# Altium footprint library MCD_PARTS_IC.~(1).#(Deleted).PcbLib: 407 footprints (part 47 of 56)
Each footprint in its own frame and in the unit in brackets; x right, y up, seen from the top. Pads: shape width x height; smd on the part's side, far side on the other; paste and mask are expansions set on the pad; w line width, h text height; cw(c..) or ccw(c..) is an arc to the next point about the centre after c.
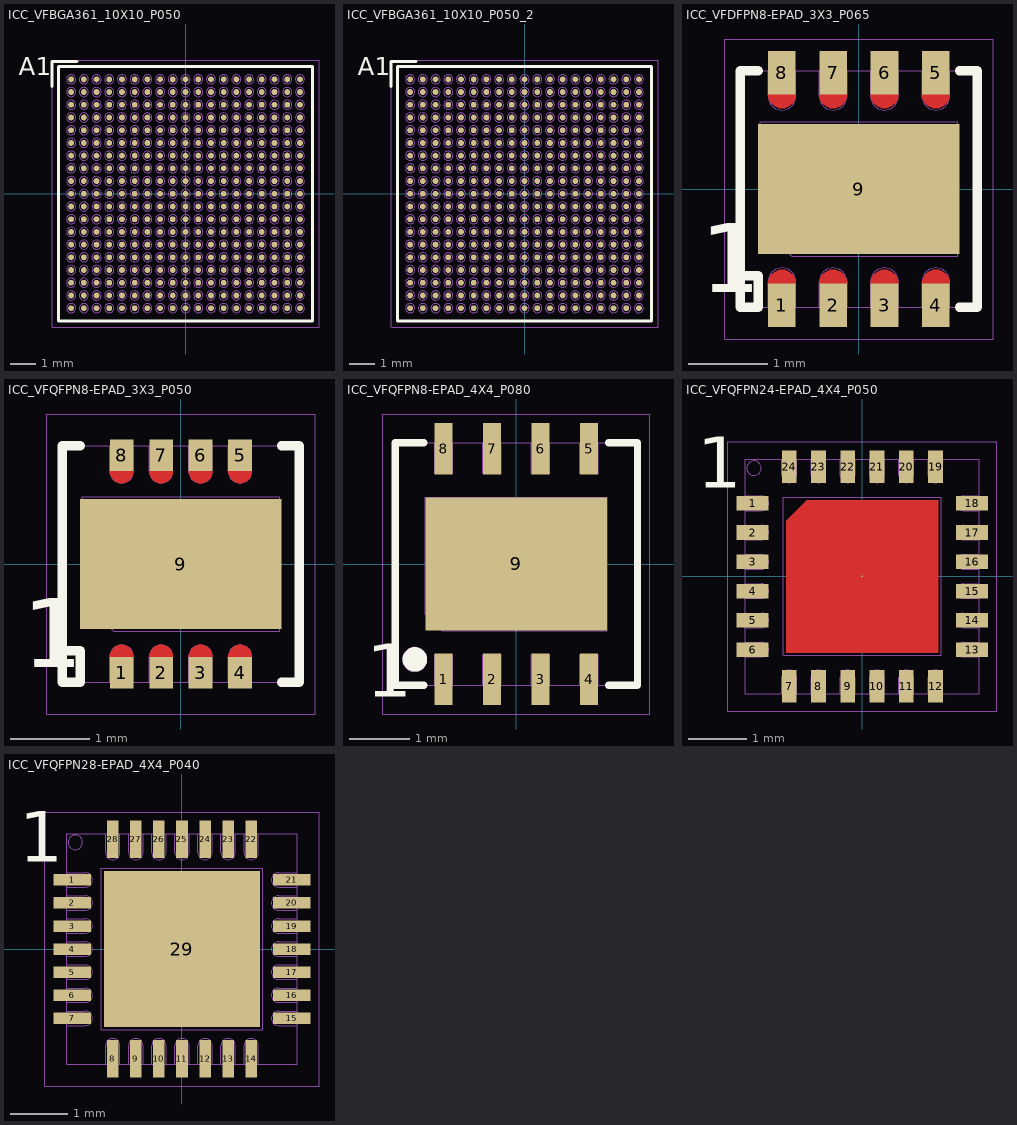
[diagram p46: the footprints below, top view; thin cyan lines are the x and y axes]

## ICC_VFBGA361_10X10_P050 [mm] "MCD-03768"
height 0.81
pads (361):
  round 0.23 smd mask+0.05: A1(-4.5,4.5) A2(-4,4.5) A3(-3.5,4.5) A4(-3,4.5) A5(-2.5,4.5) A6(-2,4.5) A7(-1.5,4.5) A8(-1,4.5) A9(-0.5,4.5) A10(0,4.5) A11(0.5,4.5) A12(1,4.5) A13(1.5,4.5) A14(2,4.5) A15(2.5,4.5) A16(3,4.5) A17(3.5,4.5) A18(4,4.5) A19(4.5,4.5) B1(-4.5,4) B2(-4,4) B3(-3.5,4) B4(-3,4) B5(-2.5,4) B6(-2,4) B7(-1.5,4) B8(-1,4) B9(-0.5,4) B10(0,4) B11(0.5,4) B12(1,4) B13(1.5,4) B14(2,4) B15(2.5,4) B16(3,4) B17(3.5,4) B18(4,4) B19(4.5,4) C1(-4.5,3.5) C2(-4,3.5) C3(-3.5,3.5) C4(-3,3.5) C5(-2.5,3.5) C6(-2,3.5) C7(-1.5,3.5) C8(-1,3.5) C9(-0.5,3.5) C10(0,3.5) C11(0.5,3.5) C12(1,3.5) C13(1.5,3.5) C14(2,3.5) C15(2.5,3.5) C16(3,3.5) C17(3.5,3.5) C18(4,3.5) C19(4.5,3.5) D1(-4.5,3) D2(-4,3) D3(-3.5,3) D4(-3,3) D5(-2.5,3) D6(-2,3) D7(-1.5,3) D8(-1,3) D9(-0.5,3) D10(0,3) D11(0.5,3) D12(1,3) D13(1.5,3) D14(2,3) D15(2.5,3) D16(3,3) D17(3.5,3) D18(4,3) D19(4.5,3) E1(-4.5,2.5) E2(-4,2.5) E3(-3.5,2.5) E4(-3,2.5) E5(-2.5,2.5) E6(-2,2.5) E7(-1.5,2.5) E8(-1,2.5) E9(-0.5,2.5) E10(0,2.5) E11(0.5,2.5) E12(1,2.5) E13(1.5,2.5) E14(2,2.5) E15(2.5,2.5) E16(3,2.5) E17(3.5,2.5) E18(4,2.5) E19(4.5,2.5) F1(-4.5,2) F2(-4,2) F3(-3.5,2) F4(-3,2) F5(-2.5,2) F6(-2,2) F7(-1.5,2) F8(-1,2) F9(-0.5,2) F10(0,2) F11(0.5,2) F12(1,2) F13(1.5,2) F14(2,2) F15(2.5,2) F16(3,2) F17(3.5,2) F18(4,2) F19(4.5,2) G1(-4.5,1.5) G2(-4,1.5) G3(-3.5,1.5) G4(-3,1.5) G5(-2.5,1.5) G6(-2,1.5) G7(-1.5,1.5) G8(-1,1.5) G9(-0.5,1.5) G10(0,1.5) G11(0.5,1.5) G12(1,1.5) G13(1.5,1.5) G14(2,1.5) G15(2.5,1.5) G16(3,1.5) G17(3.5,1.5) G18(4,1.5) G19(4.5,1.5) H1(-4.5,1) H2(-4,1) H3(-3.5,1) H4(-3,1) H5(-2.5,1) H6(-2,1) H7(-1.5,1) H8(-1,1) H9(-0.5,1) H10(0,1) H11(0.5,1) H12(1,1) H13(1.5,1) H14(2,1) H15(2.5,1) H16(3,1) H17(3.5,1) H18(4,1) H19(4.5,1) J1(-4.5,0.5) J2(-4,0.5) J3(-3.5,0.5) J4(-3,0.5) J5(-2.5,0.5) J6(-2,0.5) J7(-1.5,0.5) J8(-1,0.5) J9(-0.5,0.5) J10(0,0.5) J11(0.5,0.5) J12(1,0.5) J13(1.5,0.5) J14(2,0.5) J15(2.5,0.5) J16(3,0.5) J17(3.5,0.5) J18(4,0.5) J19(4.5,0.5) K1(-4.5,0) K2(-4,0) K3(-3.5,0) K4(-3,0) K5(-2.5,0) K6(-2,0) K7(-1.5,0) K8(-1,0) K9(-0.5,0) K10(0,0) K11(0.5,0) K12(1,0) K13(1.5,0) K14(2,0) K15(2.5,0) K16(3,0) K17(3.5,0) K18(4,0) K19(4.5,0) L1(-4.5,-0.5) L2(-4,-0.5) L3(-3.5,-0.5) L4(-3,-0.5) L5(-2.5,-0.5) L6(-2,-0.5) L7(-1.5,-0.5) L8(-1,-0.5) L9(-0.5,-0.5) L10(0,-0.5) L11(0.5,-0.5) L12(1,-0.5) L13(1.5,-0.5) L14(2,-0.5) L15(2.5,-0.5) L16(3,-0.5) L17(3.5,-0.5) L18(4,-0.5) L19(4.5,-0.5) M1(-4.5,-1) M2(-4,-1) M3(-3.5,-1) M4(-3,-1) M5(-2.5,-1) M6(-2,-1) M7(-1.5,-1) M8(-1,-1) M9(-0.5,-1) M10(0,-1) M11(0.5,-1) M12(1,-1) M13(1.5,-1) M14(2,-1) M15(2.5,-1) M16(3,-1) M17(3.5,-1) M18(4,-1) M19(4.5,-1) N1(-4.5,-1.5) N2(-4,-1.5) N3(-3.5,-1.5) N4(-3,-1.5) N5(-2.5,-1.5) N6(-2,-1.5) N7(-1.5,-1.5) N8(-1,-1.5) N9(-0.5,-1.5) N10(0,-1.5) N11(0.5,-1.5) N12(1,-1.5) N13(1.5,-1.5) N14(2,-1.5) N15(2.5,-1.5) N16(3,-1.5) N17(3.5,-1.5) N18(4,-1.5) N19(4.5,-1.5) P1(-4.5,-2) P2(-4,-2) P3(-3.5,-2) P4(-3,-2) P5(-2.5,-2) P6(-2,-2) P7(-1.5,-2) P8(-1,-2) P9(-0.5,-2) P10(0,-2) P11(0.5,-2) P12(1,-2) P13(1.5,-2) P14(2,-2) P15(2.5,-2) P16(3,-2) P17(3.5,-2) P18(4,-2) P19(4.5,-2) R1(-4.5,-2.5) R2(-4,-2.5) R3(-3.5,-2.5) R4(-3,-2.5) R5(-2.5,-2.5) R6(-2,-2.5) R7(-1.5,-2.5) R8(-1,-2.5) R9(-0.5,-2.5) R10(0,-2.5) R11(0.5,-2.5) R12(1,-2.5) R13(1.5,-2.5) R14(2,-2.5) R15(2.5,-2.5) R16(3,-2.5) R17(3.5,-2.5) R18(4,-2.5) R19(4.5,-2.5) T1(-4.5,-3) T2(-4,-3) T3(-3.5,-3) T4(-3,-3) T5(-2.5,-3) T6(-2,-3) T7(-1.5,-3) T8(-1,-3) T9(-0.5,-3) T10(0,-3) T11(0.5,-3) T12(1,-3) T13(1.5,-3) T14(2,-3) T15(2.5,-3) T16(3,-3) T17(3.5,-3) T18(4,-3) T19(4.5,-3) U1(-4.5,-3.5) U2(-4,-3.5) U3(-3.5,-3.5) U4(-3,-3.5) U5(-2.5,-3.5) U6(-2,-3.5) U7(-1.5,-3.5) U8(-1,-3.5) U9(-0.5,-3.5) U10(0,-3.5) U11(0.5,-3.5) U12(1,-3.5) U13(1.5,-3.5) U14(2,-3.5) U15(2.5,-3.5) U16(3,-3.5) U17(3.5,-3.5) U18(4,-3.5) U19(4.5,-3.5) V1(-4.5,-4) V2(-4,-4) V3(-3.5,-4) V4(-3,-4) V5(-2.5,-4) V6(-2,-4) V7(-1.5,-4) V8(-1,-4) V9(-0.5,-4) V10(0,-4) V11(0.5,-4) V12(1,-4) V13(1.5,-4) V14(2,-4) V15(2.5,-4) V16(3,-4) V17(3.5,-4) V18(4,-4) V19(4.5,-4) W1(-4.5,-4.5) W2(-4,-4.5) W3(-3.5,-4.5) W4(-3,-4.5) W5(-2.5,-4.5) W6(-2,-4.5) W7(-1.5,-4.5) W8(-1,-4.5) W9(-0.5,-4.5) W10(0,-4.5) W11(0.5,-4.5) W12(1,-4.5) W13(1.5,-4.5) W14(2,-4.5) W15(2.5,-4.5) W16(3,-4.5) W17(3.5,-4.5) W18(4,-4.5) W19(4.5,-4.5)
Top Overlay:
  lines w0.12: -5.245,4.22 -5.245,5.195 -4.27,5.195 ; -5,-5 5,-5 5,5 -5,5 -5,-5
  text "A1" at -6.55,4.425 h1.2
M14-Top Assembly:
  drawing of 365 lines, arcs and shapes, not listed
  text "'.Designator'" at 0,0 h0.75
  text "A1" at -5,4.309 h0.75
M16-Top Courtyard:
  lines w0.01: -5.25,-5.25 5.25,-5.25 5.25,5.25 -5.25,5.25 -5.25,-5.25
3D body: height 0.35, standoff -0.01, extent 4.32,-4.68 4.68,-4.32
3D body: height 0.35, standoff -0.01, extent 3.82,-4.68 4.18,-4.32
3D body: height 0.35, standoff -0.01, extent 1.32,-4.68 1.68,-4.32
3D body: height 0.35, standoff -0.01, extent 1.82,-4.68 2.18,-4.32
3D body: height 0.35, standoff -0.01, extent 2.32,-4.68 2.68,-4.32
3D body: height 0.35, standoff -0.01, extent 2.82,-4.68 3.18,-4.32
3D body: height 0.35, standoff -0.01, extent 3.32,-4.68 3.68,-4.32
3D body: height 0.35, standoff -0.01, extent -1.68,-4.68 -1.32,-4.32
3D body: height 0.35, standoff -0.01, extent -1.18,-4.68 -0.82,-4.32
3D body: height 0.35, standoff -0.01, extent -0.68,-4.68 -0.32,-4.32
3D body: height 0.35, standoff -0.01, extent -0.18,-4.68 0.18,-4.32
3D body: height 0.35, standoff -0.01, extent 0.32,-4.68 0.68,-4.32
3D body: height 0.35, standoff -0.01, extent 0.82,-4.68 1.18,-4.32
3D body: height 0.35, standoff -0.01, extent -2.18,-4.68 -1.82,-4.32
3D body: height 0.35, standoff -0.01, extent -2.68,-4.68 -2.32,-4.32
3D body: height 0.35, standoff -0.01, extent -3.18,-4.68 -2.82,-4.32
3D body: height 0.35, standoff -0.01, extent -3.68,-4.68 -3.32,-4.32
3D body: height 0.35, standoff -0.01, extent -4.18,-4.68 -3.82,-4.32
3D body: height 0.35, standoff -0.01, extent -4.68,-4.68 -4.32,-4.32
3D body: height 0.35, standoff -0.01, extent 4.32,-4.18 4.68,-3.82
3D body: height 0.35, standoff -0.01, extent 3.82,-4.18 4.18,-3.82
3D body: height 0.35, standoff -0.01, extent 1.32,-4.18 1.68,-3.82
3D body: height 0.35, standoff -0.01, extent 1.82,-4.18 2.18,-3.82
3D body: height 0.35, standoff -0.01, extent 2.32,-4.18 2.68,-3.82
3D body: height 0.35, standoff -0.01, extent 2.82,-4.18 3.18,-3.82
3D body: height 0.35, standoff -0.01, extent 3.32,-4.18 3.68,-3.82
3D body: height 0.35, standoff -0.01, extent -1.68,-4.18 -1.32,-3.82
3D body: height 0.35, standoff -0.01, extent -1.18,-4.18 -0.82,-3.82
3D body: height 0.35, standoff -0.01, extent -0.68,-4.18 -0.32,-3.82
3D body: height 0.35, standoff -0.01, extent -0.18,-4.18 0.18,-3.82
3D body: height 0.35, standoff -0.01, extent 0.32,-4.18 0.68,-3.82
3D body: height 0.35, standoff -0.01, extent 0.82,-4.18 1.18,-3.82
3D body: height 0.35, standoff -0.01, extent -2.18,-4.18 -1.82,-3.82
3D body: height 0.35, standoff -0.01, extent -2.68,-4.18 -2.32,-3.82
3D body: height 0.35, standoff -0.01, extent -3.18,-4.18 -2.82,-3.82
3D body: height 0.35, standoff -0.01, extent -3.68,-4.18 -3.32,-3.82
3D body: height 0.35, standoff -0.01, extent -4.18,-4.18 -3.82,-3.82
3D body: height 0.35, standoff -0.01, extent -4.68,-4.18 -4.32,-3.82
3D body: height 0.35, standoff -0.01, extent 4.32,-3.68 4.68,-3.32
3D body: height 0.35, standoff -0.01, extent 4.32,-3.18 4.68,-2.82
3D body: height 0.35, standoff -0.01, extent 4.32,-2.68 4.68,-2.32
3D body: height 0.35, standoff -0.01, extent 4.32,-2.18 4.68,-1.82
3D body: height 0.35, standoff -0.01, extent 4.32,-1.68 4.68,-1.32
3D body: height 0.35, standoff -0.01, extent 4.32,-1.18 4.68,-0.82
3D body: height 0.35, standoff -0.01, extent 4.32,1.82 4.68,2.18
3D body: height 0.35, standoff -0.01, extent 4.32,2.32 4.68,2.68
3D body: height 0.35, standoff -0.01, extent 4.32,2.82 4.68,3.18
3D body: height 0.35, standoff -0.01, extent 4.32,3.32 4.68,3.68
3D body: height 0.35, standoff -0.01, extent 4.32,3.82 4.68,4.18
3D body: height 0.35, standoff -0.01, extent 4.32,4.32 4.68,4.68
3D body: height 0.35, standoff -0.01, extent 4.32,1.32 4.68,1.68
3D body: height 0.35, standoff -0.01, extent 4.32,0.82 4.68,1.18
3D body: height 0.35, standoff -0.01, extent 4.32,-0.18 4.68,0.18
3D body: height 0.35, standoff -0.01, extent 4.32,-0.68 4.68,-0.32
3D body: height 0.35, standoff -0.01, extent 4.32,0.32 4.68,0.68
3D body: height 0.35, standoff -0.01, extent 3.82,-3.68 4.18,-3.32
3D body: height 0.35, standoff -0.01, extent 3.82,-3.18 4.18,-2.82
3D body: height 0.35, standoff -0.01, extent 3.82,-2.68 4.18,-2.32
3D body: height 0.35, standoff -0.01, extent 3.82,-2.18 4.18,-1.82
3D body: height 0.35, standoff -0.01, extent 3.82,-1.68 4.18,-1.32
3D body: height 0.35, standoff -0.01, extent 3.82,-1.18 4.18,-0.82
3D body: height 0.35, standoff -0.01, extent 3.82,1.82 4.18,2.18
3D body: height 0.35, standoff -0.01, extent 3.82,2.32 4.18,2.68
3D body: height 0.35, standoff -0.01, extent 3.82,2.82 4.18,3.18
3D body: height 0.35, standoff -0.01, extent 3.82,3.32 4.18,3.68
3D body: height 0.35, standoff -0.01, extent 3.82,3.82 4.18,4.18
3D body: height 0.35, standoff -0.01, extent 3.82,4.32 4.18,4.68
3D body: height 0.35, standoff -0.01, extent 3.82,1.32 4.18,1.68
3D body: height 0.35, standoff -0.01, extent 3.82,0.82 4.18,1.18
3D body: height 0.35, standoff -0.01, extent 3.82,-0.18 4.18,0.18
3D body: height 0.35, standoff -0.01, extent 3.82,-0.68 4.18,-0.32
3D body: height 0.35, standoff -0.01, extent 3.82,0.32 4.18,0.68
3D body: height 0.35, standoff -0.01, extent 0.32,-0.68 0.68,-0.32
3D body: height 0.35, standoff -0.01, extent 0.32,-0.18 0.68,0.18
3D body: height 0.35, standoff -0.01, extent 0.32,0.82 0.68,1.18
3D body: height 0.35, standoff -0.01, extent 0.32,1.32 0.68,1.68
3D body: height 0.35, standoff -0.01, extent 0.32,0.32 0.68,0.68
3D body: height 0.35, standoff -0.01, extent -0.18,-0.68 0.18,-0.32
3D body: height 0.35, standoff -0.01, extent -0.18,-0.18 0.18,0.18
3D body: height 0.35, standoff -0.01, extent -0.18,0.82 0.18,1.18
3D body: height 0.35, standoff -0.01, extent -0.18,1.32 0.18,1.68
3D body: height 0.35, standoff -0.01, extent -0.18,0.32 0.18,0.68
3D body: height 0.35, standoff -0.01, extent -0.68,-0.68 -0.32,-0.32
3D body: height 0.35, standoff -0.01, extent -0.68,-0.18 -0.32,0.18
3D body: height 0.35, standoff -0.01, extent -0.68,0.82 -0.32,1.18
3D body: height 0.35, standoff -0.01, extent -0.68,1.32 -0.32,1.68
3D body: height 0.35, standoff -0.01, extent -0.68,0.32 -0.32,0.68
3D body: height 0.35, standoff -0.01, extent -1.18,-0.68 -0.82,-0.32
3D body: height 0.35, standoff -0.01, extent -1.18,-0.18 -0.82,0.18
3D body: height 0.35, standoff -0.01, extent -1.18,0.82 -0.82,1.18
3D body: height 0.35, standoff -0.01, extent -1.18,1.32 -0.82,1.68
3D body: height 0.35, standoff -0.01, extent -1.18,0.32 -0.82,0.68
3D body: height 0.35, standoff -0.01, extent -1.68,-0.68 -1.32,-0.32
3D body: height 0.35, standoff -0.01, extent -1.68,-0.18 -1.32,0.18
3D body: height 0.35, standoff -0.01, extent -1.68,0.82 -1.32,1.18
3D body: height 0.35, standoff -0.01, extent -1.68,1.32 -1.32,1.68
3D body: height 0.35, standoff -0.01, extent -1.68,0.32 -1.32,0.68
3D body: height 0.82, standoff 0.81, extent -4.662,4.162 -4.162,4.662
3D body: height 0.35, standoff -0.01, extent 1.32,-3.68 1.68,-3.32
3D body: height 0.35, standoff -0.01, extent 1.82,-3.68 2.18,-3.32
3D body: height 0.35, standoff -0.01, extent 2.32,-3.68 2.68,-3.32
3D body: height 0.35, standoff -0.01, extent 2.82,-3.68 3.18,-3.32
3D body: height 0.35, standoff -0.01, extent 3.32,-3.68 3.68,-3.32
3D body: height 0.35, standoff -0.01, extent -1.68,-3.68 -1.32,-3.32
3D body: height 0.35, standoff -0.01, extent -1.18,-3.68 -0.82,-3.32
3D body: height 0.35, standoff -0.01, extent -0.68,-3.68 -0.32,-3.32
3D body: height 0.35, standoff -0.01, extent -0.18,-3.68 0.18,-3.32
3D body: height 0.35, standoff -0.01, extent 0.32,-3.68 0.68,-3.32
3D body: height 0.35, standoff -0.01, extent 0.82,-3.68 1.18,-3.32
3D body: height 0.35, standoff -0.01, extent -2.18,-3.68 -1.82,-3.32
3D body: height 0.35, standoff -0.01, extent -2.68,-3.68 -2.32,-3.32
3D body: height 0.35, standoff -0.01, extent -3.18,-3.68 -2.82,-3.32
3D body: height 0.35, standoff -0.01, extent -3.68,-3.68 -3.32,-3.32
3D body: height 0.35, standoff -0.01, extent -4.18,-3.68 -3.82,-3.32
3D body: height 0.35, standoff -0.01, extent 1.32,-3.18 1.68,-2.82
3D body: height 0.35, standoff -0.01, extent 1.82,-3.18 2.18,-2.82
3D body: height 0.35, standoff -0.01, extent 2.32,-3.18 2.68,-2.82
3D body: height 0.35, standoff -0.01, extent 2.82,-3.18 3.18,-2.82
3D body: height 0.35, standoff -0.01, extent 3.32,-3.18 3.68,-2.82
3D body: height 0.35, standoff -0.01, extent -1.68,-3.18 -1.32,-2.82
3D body: height 0.35, standoff -0.01, extent -1.18,-3.18 -0.82,-2.82
3D body: height 0.35, standoff -0.01, extent -0.68,-3.18 -0.32,-2.82
3D body: height 0.35, standoff -0.01, extent -0.18,-3.18 0.18,-2.82
3D body: height 0.35, standoff -0.01, extent 0.32,-3.18 0.68,-2.82
3D body: height 0.35, standoff -0.01, extent 0.82,-3.18 1.18,-2.82
3D body: height 0.35, standoff -0.01, extent -2.18,-3.18 -1.82,-2.82
3D body: height 0.35, standoff -0.01, extent -2.68,-3.18 -2.32,-2.82
3D body: height 0.35, standoff -0.01, extent -3.18,-3.18 -2.82,-2.82
3D body: height 0.35, standoff -0.01, extent -3.68,-3.18 -3.32,-2.82
3D body: height 0.35, standoff -0.01, extent -4.18,-3.18 -3.82,-2.82
3D body: height 0.35, standoff -0.01, extent 1.32,-2.68 1.68,-2.32
3D body: height 0.35, standoff -0.01, extent 1.82,-2.68 2.18,-2.32
3D body: height 0.35, standoff -0.01, extent 2.32,-2.68 2.68,-2.32
3D body: height 0.35, standoff -0.01, extent 2.82,-2.68 3.18,-2.32
3D body: height 0.35, standoff -0.01, extent 3.32,-2.68 3.68,-2.32
3D body: height 0.35, standoff -0.01, extent -1.68,-2.68 -1.32,-2.32
3D body: height 0.35, standoff -0.01, extent -1.18,-2.68 -0.82,-2.32
3D body: height 0.35, standoff -0.01, extent -0.68,-2.68 -0.32,-2.32
3D body: height 0.35, standoff -0.01, extent -0.18,-2.68 0.18,-2.32
3D body: height 0.35, standoff -0.01, extent 0.32,-2.68 0.68,-2.32
3D body: height 0.35, standoff -0.01, extent 0.82,-2.68 1.18,-2.32
3D body: height 0.35, standoff -0.01, extent -2.18,-2.68 -1.82,-2.32
3D body: height 0.35, standoff -0.01, extent -2.68,-2.68 -2.32,-2.32
3D body: height 0.35, standoff -0.01, extent -3.18,-2.68 -2.82,-2.32
3D body: height 0.35, standoff -0.01, extent -3.68,-2.68 -3.32,-2.32
3D body: height 0.35, standoff -0.01, extent -4.18,-2.68 -3.82,-2.32
3D body: height 0.35, standoff -0.01, extent 1.32,-2.18 1.68,-1.82
3D body: height 0.35, standoff -0.01, extent 1.82,-2.18 2.18,-1.82
3D body: height 0.35, standoff -0.01, extent 2.32,-2.18 2.68,-1.82
3D body: height 0.35, standoff -0.01, extent 2.82,-2.18 3.18,-1.82
3D body: height 0.35, standoff -0.01, extent 3.32,-2.18 3.68,-1.82
3D body: height 0.35, standoff -0.01, extent -1.68,-2.18 -1.32,-1.82
3D body: height 0.35, standoff -0.01, extent -1.18,-2.18 -0.82,-1.82
3D body: height 0.35, standoff -0.01, extent -0.68,-2.18 -0.32,-1.82
3D body: height 0.35, standoff -0.01, extent -0.18,-2.18 0.18,-1.82
3D body: height 0.35, standoff -0.01, extent 0.32,-2.18 0.68,-1.82
3D body: height 0.35, standoff -0.01, extent 0.82,-2.18 1.18,-1.82
3D body: height 0.35, standoff -0.01, extent -2.18,-2.18 -1.82,-1.82
3D body: height 0.35, standoff -0.01, extent -2.68,-2.18 -2.32,-1.82
3D body: height 0.35, standoff -0.01, extent -3.18,-2.18 -2.82,-1.82
3D body: height 0.35, standoff -0.01, extent -3.68,-2.18 -3.32,-1.82
3D body: height 0.35, standoff -0.01, extent -4.18,-2.18 -3.82,-1.82
3D body: height 0.35, standoff -0.01, extent 1.32,-1.68 1.68,-1.32
3D body: height 0.35, standoff -0.01, extent 1.82,-1.68 2.18,-1.32
3D body: height 0.35, standoff -0.01, extent 2.32,-1.68 2.68,-1.32
3D body: height 0.35, standoff -0.01, extent 2.82,-1.68 3.18,-1.32
3D body: height 0.35, standoff -0.01, extent 3.32,-1.68 3.68,-1.32
3D body: height 0.35, standoff -0.01, extent -1.68,-1.68 -1.32,-1.32
3D body: height 0.35, standoff -0.01, extent -1.18,-1.68 -0.82,-1.32
3D body: height 0.35, standoff -0.01, extent -0.68,-1.68 -0.32,-1.32
3D body: height 0.35, standoff -0.01, extent -0.18,-1.68 0.18,-1.32
3D body: height 0.35, standoff -0.01, extent 0.32,-1.68 0.68,-1.32
3D body: height 0.35, standoff -0.01, extent 0.82,-1.68 1.18,-1.32
3D body: height 0.35, standoff -0.01, extent -2.18,-1.68 -1.82,-1.32
3D body: height 0.35, standoff -0.01, extent -2.68,-1.68 -2.32,-1.32
3D body: height 0.35, standoff -0.01, extent -3.18,-1.68 -2.82,-1.32
3D body: height 0.35, standoff -0.01, extent -3.68,-1.68 -3.32,-1.32
3D body: height 0.35, standoff -0.01, extent -4.18,-1.68 -3.82,-1.32
3D body: height 0.35, standoff -0.01, extent 1.32,-1.18 1.68,-0.82
3D body: height 0.35, standoff -0.01, extent 1.82,-1.18 2.18,-0.82
3D body: height 0.35, standoff -0.01, extent 2.32,-1.18 2.68,-0.82
3D body: height 0.35, standoff -0.01, extent 2.82,-1.18 3.18,-0.82
3D body: height 0.35, standoff -0.01, extent 3.32,-1.18 3.68,-0.82
3D body: height 0.35, standoff -0.01, extent -1.68,-1.18 -1.32,-0.82
3D body: height 0.35, standoff -0.01, extent -1.18,-1.18 -0.82,-0.82
3D body: height 0.35, standoff -0.01, extent -0.68,-1.18 -0.32,-0.82
3D body: height 0.35, standoff -0.01, extent -0.18,-1.18 0.18,-0.82
3D body: height 0.35, standoff -0.01, extent 0.32,-1.18 0.68,-0.82
3D body: height 0.35, standoff -0.01, extent 0.82,-1.18 1.18,-0.82
3D body: height 0.35, standoff -0.01, extent -2.18,-1.18 -1.82,-0.82
3D body: height 0.35, standoff -0.01, extent -2.68,-1.18 -2.32,-0.82
3D body: height 0.35, standoff -0.01, extent -3.18,-1.18 -2.82,-0.82
3D body: height 0.35, standoff -0.01, extent -3.68,-1.18 -3.32,-0.82
3D body: height 0.35, standoff -0.01, extent -4.18,-1.18 -3.82,-0.82
3D body: height 0.35, standoff -0.01, extent 1.32,1.82 1.68,2.18
3D body: height 0.35, standoff -0.01, extent 1.82,1.82 2.18,2.18
3D body: height 0.35, standoff -0.01, extent 2.32,1.82 2.68,2.18
3D body: height 0.35, standoff -0.01, extent 2.82,1.82 3.18,2.18
3D body: height 0.35, standoff -0.01, extent 3.32,1.82 3.68,2.18
3D body: height 0.35, standoff -0.01, extent -1.68,1.82 -1.32,2.18
3D body: height 0.35, standoff -0.01, extent -1.18,1.82 -0.82,2.18
3D body: height 0.35, standoff -0.01, extent -0.68,1.82 -0.32,2.18
3D body: height 0.35, standoff -0.01, extent -0.18,1.82 0.18,2.18
3D body: height 0.35, standoff -0.01, extent 0.32,1.82 0.68,2.18
3D body: height 0.35, standoff -0.01, extent 0.82,1.82 1.18,2.18
3D body: height 0.35, standoff -0.01, extent -2.18,1.82 -1.82,2.18
3D body: height 0.35, standoff -0.01, extent -2.68,1.82 -2.32,2.18
3D body: height 0.35, standoff -0.01, extent -3.18,1.82 -2.82,2.18
3D body: height 0.35, standoff -0.01, extent -3.68,1.82 -3.32,2.18
3D body: height 0.35, standoff -0.01, extent -4.18,1.82 -3.82,2.18
3D body: height 0.35, standoff -0.01, extent 1.32,2.32 1.68,2.68
3D body: height 0.35, standoff -0.01, extent 1.82,2.32 2.18,2.68
3D body: height 0.35, standoff -0.01, extent 2.32,2.32 2.68,2.68
3D body: height 0.35, standoff -0.01, extent 2.82,2.32 3.18,2.68
3D body: height 0.35, standoff -0.01, extent 3.32,2.32 3.68,2.68
3D body: height 0.35, standoff -0.01, extent -1.68,2.32 -1.32,2.68
3D body: height 0.35, standoff -0.01, extent -1.18,2.32 -0.82,2.68
3D body: height 0.35, standoff -0.01, extent -0.68,2.32 -0.32,2.68
3D body: height 0.35, standoff -0.01, extent -0.18,2.32 0.18,2.68
3D body: height 0.35, standoff -0.01, extent 0.32,2.32 0.68,2.68
3D body: height 0.35, standoff -0.01, extent 0.82,2.32 1.18,2.68
3D body: height 0.35, standoff -0.01, extent -2.18,2.32 -1.82,2.68
3D body: height 0.35, standoff -0.01, extent -2.68,2.32 -2.32,2.68
3D body: height 0.35, standoff -0.01, extent -3.18,2.32 -2.82,2.68
3D body: height 0.35, standoff -0.01, extent -3.68,2.32 -3.32,2.68
3D body: height 0.35, standoff -0.01, extent -4.18,2.32 -3.82,2.68
3D body: height 0.35, standoff -0.01, extent 1.32,2.82 1.68,3.18
3D body: height 0.35, standoff -0.01, extent 1.82,2.82 2.18,3.18
3D body: height 0.35, standoff -0.01, extent 2.32,2.82 2.68,3.18
3D body: height 0.35, standoff -0.01, extent 2.82,2.82 3.18,3.18
3D body: height 0.35, standoff -0.01, extent 3.32,2.82 3.68,3.18
3D body: height 0.35, standoff -0.01, extent -1.68,2.82 -1.32,3.18
3D body: height 0.35, standoff -0.01, extent -1.18,2.82 -0.82,3.18
3D body: height 0.35, standoff -0.01, extent -0.68,2.82 -0.32,3.18
3D body: height 0.35, standoff -0.01, extent -0.18,2.82 0.18,3.18
3D body: height 0.35, standoff -0.01, extent 0.32,2.82 0.68,3.18
3D body: height 0.35, standoff -0.01, extent 0.82,2.82 1.18,3.18
3D body: height 0.35, standoff -0.01, extent -2.18,2.82 -1.82,3.18
3D body: height 0.35, standoff -0.01, extent -2.68,2.82 -2.32,3.18
3D body: height 0.35, standoff -0.01, extent -3.18,2.82 -2.82,3.18
3D body: height 0.35, standoff -0.01, extent -3.68,2.82 -3.32,3.18
3D body: height 0.35, standoff -0.01, extent -4.18,2.82 -3.82,3.18
3D body: height 0.35, standoff -0.01, extent 1.32,3.32 1.68,3.68
3D body: height 0.35, standoff -0.01, extent 1.82,3.32 2.18,3.68
3D body: height 0.35, standoff -0.01, extent 2.32,3.32 2.68,3.68
3D body: height 0.35, standoff -0.01, extent 2.82,3.32 3.18,3.68
3D body: height 0.35, standoff -0.01, extent 3.32,3.32 3.68,3.68
3D body: height 0.35, standoff -0.01, extent -1.68,3.32 -1.32,3.68
3D body: height 0.35, standoff -0.01, extent -1.18,3.32 -0.82,3.68
3D body: height 0.35, standoff -0.01, extent -0.68,3.32 -0.32,3.68
3D body: height 0.35, standoff -0.01, extent -0.18,3.32 0.18,3.68
3D body: height 0.35, standoff -0.01, extent 0.32,3.32 0.68,3.68
3D body: height 0.35, standoff -0.01, extent 0.82,3.32 1.18,3.68
3D body: height 0.35, standoff -0.01, extent -2.18,3.32 -1.82,3.68
3D body: height 0.35, standoff -0.01, extent -2.68,3.32 -2.32,3.68
3D body: height 0.35, standoff -0.01, extent -3.18,3.32 -2.82,3.68
3D body: height 0.35, standoff -0.01, extent -3.68,3.32 -3.32,3.68
3D body: height 0.35, standoff -0.01, extent -4.18,3.32 -3.82,3.68
3D body: height 0.35, standoff -0.01, extent 1.32,3.82 1.68,4.18
3D body: height 0.35, standoff -0.01, extent 1.82,3.82 2.18,4.18
3D body: height 0.35, standoff -0.01, extent 2.32,3.82 2.68,4.18
3D body: height 0.35, standoff -0.01, extent 2.82,3.82 3.18,4.18
3D body: height 0.35, standoff -0.01, extent 3.32,3.82 3.68,4.18
3D body: height 0.35, standoff -0.01, extent -1.68,3.82 -1.32,4.18
3D body: height 0.35, standoff -0.01, extent -1.18,3.82 -0.82,4.18
3D body: height 0.35, standoff -0.01, extent -0.68,3.82 -0.32,4.18
3D body: height 0.35, standoff -0.01, extent -0.18,3.82 0.18,4.18
3D body: height 0.35, standoff -0.01, extent 0.32,3.82 0.68,4.18
3D body: height 0.35, standoff -0.01, extent 0.82,3.82 1.18,4.18
3D body: height 0.35, standoff -0.01, extent -2.18,3.82 -1.82,4.18
3D body: height 0.35, standoff -0.01, extent -2.68,3.82 -2.32,4.18
3D body: height 0.35, standoff -0.01, extent -3.18,3.82 -2.82,4.18
3D body: height 0.35, standoff -0.01, extent -3.68,3.82 -3.32,4.18
3D body: height 0.35, standoff -0.01, extent -4.18,3.82 -3.82,4.18
3D body: height 0.35, standoff -0.01, extent 1.32,4.32 1.68,4.68
3D body: height 0.35, standoff -0.01, extent 1.82,4.32 2.18,4.68
3D body: height 0.35, standoff -0.01, extent 2.32,4.32 2.68,4.68
3D body: height 0.35, standoff -0.01, extent 2.82,4.32 3.18,4.68
3D body: height 0.35, standoff -0.01, extent 3.32,4.32 3.68,4.68
3D body: height 0.35, standoff -0.01, extent -1.68,4.32 -1.32,4.68
3D body: height 0.35, standoff -0.01, extent -1.18,4.32 -0.82,4.68
3D body: height 0.35, standoff -0.01, extent -0.68,4.32 -0.32,4.68
3D body: height 0.35, standoff -0.01, extent -0.18,4.32 0.18,4.68
3D body: height 0.35, standoff -0.01, extent 0.32,4.32 0.68,4.68
3D body: height 0.35, standoff -0.01, extent 0.82,4.32 1.18,4.68
3D body: height 0.35, standoff -0.01, extent 0.82,1.32 1.18,1.68
3D body: height 0.35, standoff -0.01, extent 1.32,1.32 1.68,1.68
3D body: height 0.35, standoff -0.01, extent 1.82,1.32 2.18,1.68
3D body: height 0.35, standoff -0.01, extent 2.32,1.32 2.68,1.68
3D body: height 0.35, standoff -0.01, extent 2.82,1.32 3.18,1.68
3D body: height 0.35, standoff -0.01, extent 3.32,1.32 3.68,1.68
3D body: height 0.35, standoff -0.01, extent 0.82,0.82 1.18,1.18
3D body: height 0.35, standoff -0.01, extent 1.32,0.82 1.68,1.18
3D body: height 0.35, standoff -0.01, extent 1.82,0.82 2.18,1.18
3D body: height 0.35, standoff -0.01, extent 2.32,0.82 2.68,1.18
3D body: height 0.35, standoff -0.01, extent 2.82,0.82 3.18,1.18
3D body: height 0.35, standoff -0.01, extent 3.32,0.82 3.68,1.18
3D body: height 0.35, standoff -0.01, extent 0.82,-0.18 1.18,0.18
3D body: height 0.35, standoff -0.01, extent 1.32,-0.18 1.68,0.18
3D body: height 0.35, standoff -0.01, extent 1.82,-0.18 2.18,0.18
3D body: height 0.35, standoff -0.01, extent 2.32,-0.18 2.68,0.18
3D body: height 0.35, standoff -0.01, extent 2.82,-0.18 3.18,0.18
3D body: height 0.35, standoff -0.01, extent 3.32,-0.18 3.68,0.18
3D body: height 0.35, standoff -0.01, extent 0.82,-0.68 1.18,-0.32
3D body: height 0.35, standoff -0.01, extent 1.32,-0.68 1.68,-0.32
3D body: height 0.35, standoff -0.01, extent 1.82,-0.68 2.18,-0.32
3D body: height 0.35, standoff -0.01, extent 2.32,-0.68 2.68,-0.32
3D body: height 0.35, standoff -0.01, extent 2.82,-0.68 3.18,-0.32
3D body: height 0.35, standoff -0.01, extent 3.32,-0.68 3.68,-0.32
3D body: height 0.35, standoff -0.01, extent -2.18,-0.68 -1.82,-0.32
3D body: height 0.35, standoff -0.01, extent -2.68,-0.68 -2.32,-0.32
3D body: height 0.35, standoff -0.01, extent -3.18,-0.68 -2.82,-0.32
3D body: height 0.35, standoff -0.01, extent -3.68,-0.68 -3.32,-0.32
3D body: height 0.35, standoff -0.01, extent -4.18,-0.68 -3.82,-0.32
3D body: height 0.35, standoff -0.01, extent -2.18,-0.18 -1.82,0.18
3D body: height 0.35, standoff -0.01, extent -2.68,-0.18 -2.32,0.18
3D body: height 0.35, standoff -0.01, extent -3.18,-0.18 -2.82,0.18
3D body: height 0.35, standoff -0.01, extent -3.68,-0.18 -3.32,0.18
3D body: height 0.35, standoff -0.01, extent -4.18,-0.18 -3.82,0.18
3D body: height 0.35, standoff -0.01, extent -2.18,0.82 -1.82,1.18
3D body: height 0.35, standoff -0.01, extent -2.68,0.82 -2.32,1.18
3D body: height 0.35, standoff -0.01, extent -3.18,0.82 -2.82,1.18
3D body: height 0.35, standoff -0.01, extent -3.68,0.82 -3.32,1.18
3D body: height 0.35, standoff -0.01, extent -4.18,0.82 -3.82,1.18
3D body: height 0.35, standoff -0.01, extent -2.18,1.32 -1.82,1.68
3D body: height 0.35, standoff -0.01, extent -2.68,1.32 -2.32,1.68
3D body: height 0.35, standoff -0.01, extent -3.18,1.32 -2.82,1.68
3D body: height 0.35, standoff -0.01, extent -3.68,1.32 -3.32,1.68
3D body: height 0.35, standoff -0.01, extent -4.18,1.32 -3.82,1.68
3D body: height 0.35, standoff -0.01, extent -2.18,4.32 -1.82,4.68
3D body: height 0.35, standoff -0.01, extent -2.68,4.32 -2.32,4.68
3D body: height 0.35, standoff -0.01, extent -3.18,4.32 -2.82,4.68
3D body: height 0.35, standoff -0.01, extent -3.68,4.32 -3.32,4.68
3D body: height 0.35, standoff -0.01, extent -4.18,4.32 -3.82,4.68
3D body: height 0.81, standoff 0.25, extent -5,-5 5,5
3D body: height 0.35, standoff -0.01, extent -4.68,4.32 -4.32,4.68
3D body: height 0.35, standoff -0.01, extent -4.68,2.82 -4.32,3.18
3D body: height 0.35, standoff -0.01, extent -4.68,3.82 -4.32,4.18
3D body: height 0.35, standoff -0.01, extent -4.68,3.32 -4.32,3.68
3D body: height 0.35, standoff -0.01, extent -4.68,2.32 -4.32,2.68
3D body: height 0.35, standoff -0.01, extent -4.68,1.82 -4.32,2.18
3D body: height 0.35, standoff -0.01, extent -4.68,1.32 -4.32,1.68
3D body: height 0.35, standoff -0.01, extent -4.68,0.82 -4.32,1.18
3D body: height 0.35, standoff -0.01, extent -4.68,-1.18 -4.32,-0.82
3D body: height 0.35, standoff -0.01, extent -4.68,-1.68 -4.32,-1.32
3D body: height 0.35, standoff -0.01, extent -4.68,-2.18 -4.32,-1.82
3D body: height 0.35, standoff -0.01, extent -4.68,-2.68 -4.32,-2.32
3D body: height 0.35, standoff -0.01, extent -4.68,-0.68 -4.32,-0.32
3D body: height 0.35, standoff -0.01, extent -4.68,-0.18 -4.32,0.18
3D body: height 0.35, standoff -0.01, extent -4.68,-3.18 -4.32,-2.82
3D body: height 0.35, standoff -0.01, extent -4.68,-3.68 -4.32,-3.32
3D body: height 0.35, standoff -0.01, extent 1.82,0.32 2.18,0.68
3D body: height 0.35, standoff -0.01, extent 1.32,0.32 1.68,0.68
3D body: height 0.35, standoff -0.01, extent -3.18,0.32 -2.82,0.68
3D body: height 0.35, standoff -0.01, extent -3.68,0.32 -3.32,0.68
3D body: height 0.35, standoff -0.01, extent -2.68,0.32 -2.32,0.68
3D body: height 0.35, standoff -0.01, extent -4.18,0.32 -3.82,0.68
3D body: height 0.35, standoff -0.01, extent -2.18,0.32 -1.82,0.68
3D body: height 0.35, standoff -0.01, extent -4.68,0.32 -4.32,0.68
3D body: height 0.35, standoff -0.01, extent 3.32,0.32 3.68,0.68
3D body: height 0.35, standoff -0.01, extent 2.82,0.32 3.18,0.68
3D body: height 0.35, standoff -0.01, extent 2.32,0.32 2.68,0.68
3D body: height 0.35, standoff -0.01, extent 0.82,0.32 1.18,0.68

## ICC_VFBGA361_10X10_P050_2 [mm] "MCD-03768"
height 0.81
pads (361):
  round 0.23 smd mask+0.05: A1(-4.5,4.5) A2(-4,4.5) A3(-3.5,4.5) A4(-3,4.5) A5(-2.5,4.5) A6(-2,4.5) A7(-1.5,4.5) A8(-1,4.5) A9(-0.5,4.5) A10(0,4.5) A11(0.5,4.5) A12(1,4.5) A13(1.5,4.5) A14(2,4.5) A15(2.5,4.5) A16(3,4.5) A17(3.5,4.5) A18(4,4.5) A19(4.5,4.5) B1(-4.5,4) B2(-4,4) B3(-3.5,4) B4(-3,4) B5(-2.5,4) B6(-2,4) B7(-1.5,4) B8(-1,4) B9(-0.5,4) B10(0,4) B11(0.5,4) B12(1,4) B13(1.5,4) B14(2,4) B15(2.5,4) B16(3,4) B17(3.5,4) B18(4,4) B19(4.5,4) C1(-4.5,3.5) C2(-4,3.5) C3(-3.5,3.5) C4(-3,3.5) C5(-2.5,3.5) C6(-2,3.5) C7(-1.5,3.5) C8(-1,3.5) C9(-0.5,3.5) C10(0,3.5) C11(0.5,3.5) C12(1,3.5) C13(1.5,3.5) C14(2,3.5) C15(2.5,3.5) C16(3,3.5) C17(3.5,3.5) C18(4,3.5) C19(4.5,3.5) D1(-4.5,3) D2(-4,3) D3(-3.5,3) D4(-3,3) D5(-2.5,3) D6(-2,3) D7(-1.5,3) D8(-1,3) D9(-0.5,3) D10(0,3) D11(0.5,3) D12(1,3) D13(1.5,3) D14(2,3) D15(2.5,3) D16(3,3) D17(3.5,3) D18(4,3) D19(4.5,3) E1(-4.5,2.5) E2(-4,2.5) E3(-3.5,2.5) E4(-3,2.5) E5(-2.5,2.5) E6(-2,2.5) E7(-1.5,2.5) E8(-1,2.5) E9(-0.5,2.5) E10(0,2.5) E11(0.5,2.5) E12(1,2.5) E13(1.5,2.5) E14(2,2.5) E15(2.5,2.5) E16(3,2.5) E17(3.5,2.5) E18(4,2.5) E19(4.5,2.5) F1(-4.5,2) F2(-4,2) F3(-3.5,2) F4(-3,2) F5(-2.5,2) F6(-2,2) F7(-1.5,2) F8(-1,2) F9(-0.5,2) F10(0,2) F11(0.5,2) F12(1,2) F13(1.5,2) F14(2,2) F15(2.5,2) F16(3,2) F17(3.5,2) F18(4,2) F19(4.5,2) G1(-4.5,1.5) G2(-4,1.5) G3(-3.5,1.5) G4(-3,1.5) G5(-2.5,1.5) G6(-2,1.5) G7(-1.5,1.5) G8(-1,1.5) G9(-0.5,1.5) G10(0,1.5) G11(0.5,1.5) G12(1,1.5) G13(1.5,1.5) G14(2,1.5) G15(2.5,1.5) G16(3,1.5) G17(3.5,1.5) G18(4,1.5) G19(4.5,1.5) H1(-4.5,1) H2(-4,1) H3(-3.5,1) H4(-3,1) H5(-2.5,1) H6(-2,1) H7(-1.5,1) H8(-1,1) H9(-0.5,1) H10(0,1) H11(0.5,1) H12(1,1) H13(1.5,1) H14(2,1) H15(2.5,1) H16(3,1) H17(3.5,1) H18(4,1) H19(4.5,1) J1(-4.5,0.5) J2(-4,0.5) J3(-3.5,0.5) J4(-3,0.5) J5(-2.5,0.5) J6(-2,0.5) J7(-1.5,0.5) J8(-1,0.5) J9(-0.5,0.5) J10(0,0.5) J11(0.5,0.5) J12(1,0.5) J13(1.5,0.5) J14(2,0.5) J15(2.5,0.5) J16(3,0.5) J17(3.5,0.5) J18(4,0.5) J19(4.5,0.5) K1(-4.5,0) K2(-4,0) K3(-3.5,0) K4(-3,0) K5(-2.5,0) K6(-2,0) K7(-1.5,0) K8(-1,0) K9(-0.5,0) K10(0,0) K11(0.5,0) K12(1,0) K13(1.5,0) K14(2,0) K15(2.5,0) K16(3,0) K17(3.5,0) K18(4,0) K19(4.5,0) L1(-4.5,-0.5) L2(-4,-0.5) L3(-3.5,-0.5) L4(-3,-0.5) L5(-2.5,-0.5) L6(-2,-0.5) L7(-1.5,-0.5) L8(-1,-0.5) L9(-0.5,-0.5) L10(0,-0.5) L11(0.5,-0.5) L12(1,-0.5) L13(1.5,-0.5) L14(2,-0.5) L15(2.5,-0.5) L16(3,-0.5) L17(3.5,-0.5) L18(4,-0.5) L19(4.5,-0.5) M1(-4.5,-1) M2(-4,-1) M3(-3.5,-1) M4(-3,-1) M5(-2.5,-1) M6(-2,-1) M7(-1.5,-1) M8(-1,-1) M9(-0.5,-1) M10(0,-1) M11(0.5,-1) M12(1,-1) M13(1.5,-1) M14(2,-1) M15(2.5,-1) M16(3,-1) M17(3.5,-1) M18(4,-1) M19(4.5,-1) N1(-4.5,-1.5) N2(-4,-1.5) N3(-3.5,-1.5) N4(-3,-1.5) N5(-2.5,-1.5) N6(-2,-1.5) N7(-1.5,-1.5) N8(-1,-1.5) N9(-0.5,-1.5) N10(0,-1.5) N11(0.5,-1.5) N12(1,-1.5) N13(1.5,-1.5) N14(2,-1.5) N15(2.5,-1.5) N16(3,-1.5) N17(3.5,-1.5) N18(4,-1.5) N19(4.5,-1.5) P1(-4.5,-2) P2(-4,-2) P3(-3.5,-2) P4(-3,-2) P5(-2.5,-2) P6(-2,-2) P7(-1.5,-2) P8(-1,-2) P9(-0.5,-2) P10(0,-2) P11(0.5,-2) P12(1,-2) P13(1.5,-2) P14(2,-2) P15(2.5,-2) P16(3,-2) P17(3.5,-2) P18(4,-2) P19(4.5,-2) R1(-4.5,-2.5) R2(-4,-2.5) R3(-3.5,-2.5) R4(-3,-2.5) R5(-2.5,-2.5) R6(-2,-2.5) R7(-1.5,-2.5) R8(-1,-2.5) R9(-0.5,-2.5) R10(0,-2.5) R11(0.5,-2.5) R12(1,-2.5) R13(1.5,-2.5) R14(2,-2.5) R15(2.5,-2.5) R16(3,-2.5) R17(3.5,-2.5) R18(4,-2.5) R19(4.5,-2.5) T1(-4.5,-3) T2(-4,-3) T3(-3.5,-3) T4(-3,-3) T5(-2.5,-3) T6(-2,-3) T7(-1.5,-3) T8(-1,-3) T9(-0.5,-3) T10(0,-3) T11(0.5,-3) T12(1,-3) T13(1.5,-3) T14(2,-3) T15(2.5,-3) T16(3,-3) T17(3.5,-3) T18(4,-3) T19(4.5,-3) U1(-4.5,-3.5) U2(-4,-3.5) U3(-3.5,-3.5) U4(-3,-3.5) U5(-2.5,-3.5) U6(-2,-3.5) U7(-1.5,-3.5) U8(-1,-3.5) U9(-0.5,-3.5) U10(0,-3.5) U11(0.5,-3.5) U12(1,-3.5) U13(1.5,-3.5) U14(2,-3.5) U15(2.5,-3.5) U16(3,-3.5) U17(3.5,-3.5) U18(4,-3.5) U19(4.5,-3.5) V1(-4.5,-4) V2(-4,-4) V3(-3.5,-4) V4(-3,-4) V5(-2.5,-4) V6(-2,-4) V7(-1.5,-4) V8(-1,-4) V9(-0.5,-4) V10(0,-4) V11(0.5,-4) V12(1,-4) V13(1.5,-4) V14(2,-4) V15(2.5,-4) V16(3,-4) V17(3.5,-4) V18(4,-4) V19(4.5,-4) W1(-4.5,-4.5) W2(-4,-4.5) W3(-3.5,-4.5) W4(-3,-4.5) W5(-2.5,-4.5) W6(-2,-4.5) W7(-1.5,-4.5) W8(-1,-4.5) W9(-0.5,-4.5) W10(0,-4.5) W11(0.5,-4.5) W12(1,-4.5) W13(1.5,-4.5) W14(2,-4.5) W15(2.5,-4.5) W16(3,-4.5) W17(3.5,-4.5) W18(4,-4.5) W19(4.5,-4.5)
Top Overlay:
  lines w0.12: -5.245,4.22 -5.245,5.195 -4.27,5.195 ; -5,-5 -5,5 5,5 5,-5 -5,-5
  text "A1" at -6.55,4.425 h1.2
M14-Top Assembly:
  drawing of 365 lines, arcs and shapes, not listed
  text "A1" at -5,4.309 h0.75
  text "'.Designator'" at 0,0 h0.75
M16-Top Courtyard:
  lines w0.01: -5.25,-5.25 -5.25,5.25 5.25,5.25 5.25,-5.25 -5.25,-5.25
3D body "ICC_VFBGA361_10X10_P050.step": height 0.81, standoff 0, extent -5,-5 5,5

## ICC_VFDFPN8-EPAD_3X3_P065 [mm] "MCD-02243"
height 1
pads (9):
  rect 0.35x0.55 smd mask+0.05: 1(-0.975,-1.475) 2(-0.325,-1.475) 3(0.325,-1.475) 4(0.975,-1.475) 5(0.975,1.475) 6(0.325,1.475) 7(-0.325,1.475) 8(-0.975,1.475)
  rect 2.55x1.65 smd mask+0.05: 9(0,0)
Top Layer:
  region: -1.15,1.2 -1.15,1.165 -1.123,1.101 -1.074,1.052 -1.01,1.025 -0.975,1.025 -0.94,1.025 -0.876,1.052 -0.827,1.101 -0.8,1.165 -0.8,1.2
  region: -0.5,1.2 -0.5,1.165 -0.473,1.101 -0.424,1.052 -0.36,1.025 -0.325,1.025 -0.29,1.025 -0.226,1.052 -0.177,1.101 -0.15,1.165 -0.15,1.2
  region: 0.15,1.2 0.15,1.165 0.177,1.101 0.226,1.052 0.29,1.025 0.325,1.025 0.36,1.025 0.424,1.052 0.473,1.101 0.5,1.165 0.5,1.2
  region: 0.8,1.2 0.8,1.165 0.827,1.101 0.876,1.052 0.94,1.025 0.975,1.025 1.01,1.025 1.074,1.052 1.123,1.101 1.15,1.165 1.15,1.2
  region: 1.15,-1.2 1.15,-1.165 1.123,-1.101 1.074,-1.052 1.01,-1.025 0.975,-1.025 0.94,-1.025 0.876,-1.052 0.827,-1.101 0.8,-1.165 0.8,-1.2
  region: 0.5,-1.2 0.5,-1.165 0.473,-1.101 0.424,-1.052 0.36,-1.025 0.325,-1.025 0.29,-1.025 0.226,-1.052 0.177,-1.101 0.15,-1.165 0.15,-1.2
  region: -0.15,-1.2 -0.15,-1.165 -0.177,-1.101 -0.226,-1.052 -0.29,-1.025 -0.325,-1.025 -0.36,-1.025 -0.424,-1.052 -0.473,-1.101 -0.5,-1.165 -0.5,-1.2
  region: -0.8,-1.2 -0.8,-1.165 -0.827,-1.101 -0.876,-1.052 -0.94,-1.025 -0.975,-1.025 -1.01,-1.025 -1.074,-1.052 -1.123,-1.101 -1.15,-1.165 -1.15,-1.2
Top Overlay:
  lines w0.12: -1.5,-1.1 -1.275,-1.1 -1.275,-1.5 -1.5,-1.5 -1.5,1.5 ; -1.5,1.475 -1.475,1.5 -1.275,1.5 ; 1.275,-1.5 1.5,-1.5 1.5,1.5 1.275,1.5
  text "1" at -2,-1.6 h1.5
M14-Top Assembly:
  lines w0.01: -1.15,-1.5 -1.15,-1.175 cw(c-0.975,-1.175) -0.975,-1 cw(c-0.975,-1.175) -0.8,-1.175 -0.8,-1.5 ; -1.15,1.5 -1.15,1.175 ccw(c-0.975,1.175) -0.975,1 ccw(c-0.975,1.175) -0.8,1.175 -0.8,1.5 ; -0.5,-1.5 -0.5,-1.175 cw(c-0.325,-1.175) -0.325,-1 cw(c-0.325,-1.175) -0.15,-1.175 -0.15,-1.5 ; -0.5,1.5 -0.5,1.175 ccw(c-0.325,1.175) -0.325,1 ccw(c-0.325,1.175) -0.15,1.175 -0.15,1.5 ; 0.15,-1.5 0.15,-1.175 cw(c0.325,-1.175) 0.325,-1 cw(c0.325,-1.175) 0.5,-1.175 0.5,-1.5 ; 0.15,1.5 0.15,1.175 ccw(c0.325,1.175) 0.325,1 ccw(c0.325,1.175) 0.5,1.175 0.5,1.5 ; 0.8,-1.5 0.8,-1.175 cw(c0.975,-1.175) 0.975,-1 cw(c0.975,-1.175) 1.15,-1.175 1.15,-1.5 ; 0.8,1.5 0.8,1.175 ccw(c0.975,1.175) 0.975,1 ccw(c0.975,1.175) 1.15,1.175 1.15,1.5 ; -1.5,-1.5 1.5,-1.5 1.5,1.5 -1.5,1.5 -1.5,-1.5 ; -1.25,-0.45 -1.25,0.85 1.25,0.85 1.25,-0.85 -0.85,-0.85 -1.25,-0.45
  text "1" at -1.05,-1.425 h0.5
  text "4" at 0.85,-1.425 h0.5
  text "EP" at -0.25,-0.125 h0.5
  text "5" at 0.875,1.125 h0.5
  text "8" at -1.075,1.125 h0.5
  text "'.Designator'" at -2,-0.5 h0.75
M16-Top Courtyard:
  lines w0.01: -1.7,-1.9 1.7,-1.9 1.7,1.9 -1.7,1.9 -1.7,-1.9
3D body: height 1, standoff 0, extent -1.5,-1.5 1.5,1.5
3D body "User Library-DFN8N_65.STEP": height 0.9, standoff 0, extent -1.49,-1.5 1.5,1.5

## ICC_VFQFPN8-EPAD_3X3_P050 [mm] "MCD-02244"
height 1
pads (9):
  rect 0.3x0.4 smd mask+0.05: 1(-0.75,-1.375) 2(-0.25,-1.375) 3(0.25,-1.375) 4(0.75,-1.375) 5(0.75,1.375) 6(0.25,1.375) 7(-0.25,1.375) 8(-0.75,1.375)
  rect 2.55x1.65 smd mask+0.05: 9(0,0)
Top Layer:
  region: 0.9,-1.175 0.9,-1.145 0.877,-1.09 0.835,-1.048 0.78,-1.025 0.75,-1.025 0.72,-1.025 0.665,-1.048 0.623,-1.09 0.6,-1.145 0.6,-1.175
  region: 0.4,-1.175 0.4,-1.145 0.377,-1.09 0.335,-1.048 0.28,-1.025 0.25,-1.025 0.22,-1.025 0.165,-1.048 0.123,-1.09 0.1,-1.145 0.1,-1.175
  region: -0.1,-1.175 -0.1,-1.145 -0.123,-1.09 -0.165,-1.048 -0.22,-1.025 -0.25,-1.025 -0.28,-1.025 -0.335,-1.048 -0.377,-1.09 -0.4,-1.145 -0.4,-1.175
  region: -0.6,-1.175 -0.6,-1.145 -0.623,-1.09 -0.665,-1.048 -0.72,-1.025 -0.75,-1.025 -0.78,-1.025 -0.835,-1.048 -0.877,-1.09 -0.9,-1.145 -0.9,-1.175
  region: -0.9,1.175 -0.9,1.145 -0.877,1.09 -0.835,1.048 -0.78,1.025 -0.75,1.025 -0.72,1.025 -0.665,1.048 -0.623,1.09 -0.6,1.145 -0.6,1.175
  region: -0.4,1.175 -0.4,1.145 -0.377,1.09 -0.335,1.048 -0.28,1.025 -0.25,1.025 -0.22,1.025 -0.165,1.048 -0.123,1.09 -0.1,1.145 -0.1,1.175
  region: 0.1,1.175 0.1,1.145 0.123,1.09 0.165,1.048 0.22,1.025 0.25,1.025 0.28,1.025 0.335,1.048 0.377,1.09 0.4,1.145 0.4,1.175
  region: 0.6,1.175 0.6,1.145 0.623,1.09 0.665,1.048 0.72,1.025 0.75,1.025 0.78,1.025 0.835,1.048 0.877,1.09 0.9,1.145 0.9,1.175
Top Overlay:
  lines w0.12: -1.5,-1.1 -1.275,-1.1 -1.275,-1.5 -1.5,-1.5 -1.5,1.5 ; -1.5,1.475 -1.475,1.5 -1.275,1.5 ; 1.275,-1.5 1.5,-1.5 1.5,1.5 1.275,1.5
  text "1" at -2,-1.6 h1.5
M14-Top Assembly:
  lines w0.01: -0.9,-1.5 -0.9,-1.175 cw(c-0.75,-1.175) -0.75,-1.025 cw(c-0.75,-1.175) -0.6,-1.175 -0.6,-1.5 ; -0.9,1.5 -0.9,1.175 ccw(c-0.75,1.175) -0.75,1.025 ccw(c-0.75,1.175) -0.6,1.175 -0.6,1.5 ; -0.4,-1.5 -0.4,-1.175 cw(c-0.25,-1.175) -0.25,-1.025 cw(c-0.25,-1.175) -0.1,-1.175 -0.1,-1.5 ; -0.4,1.5 -0.4,1.175 ccw(c-0.25,1.175) -0.25,1.025 ccw(c-0.25,1.175) -0.1,1.175 -0.1,1.5 ; 0.1,-1.5 0.1,-1.175 cw(c0.25,-1.175) 0.25,-1.025 cw(c0.25,-1.175) 0.4,-1.175 0.4,-1.5 ; 0.1,1.5 0.1,1.175 ccw(c0.25,1.175) 0.25,1.025 ccw(c0.25,1.175) 0.4,1.175 0.4,1.5 ; 0.6,-1.5 0.6,-1.175 cw(c0.75,-1.175) 0.75,-1.025 cw(c0.75,-1.175) 0.9,-1.175 0.9,-1.5 ; 0.6,1.5 0.6,1.175 ccw(c0.75,1.175) 0.75,1.025 ccw(c0.75,1.175) 0.9,1.175 0.9,1.5 ; -1.5,-1.5 -1.5,1.5 1.5,1.5 1.5,-1.5 -1.5,-1.5 ; -1.25,-0.45 -0.85,-0.85 1.25,-0.85 1.25,0.85 -1.25,0.85 -1.25,-0.45
  text "1" at -0.825,-1.45 h0.5
  text "2" at -0.35,-1.45 h0.5
  text "3" at 0.15,-1.45 h0.5
  text "4" at 0.625,-1.45 h0.5
  text "8" at -0.85,1.125 h0.5
  text "5" at 0.65,1.125 h0.5
  text "7" at -0.35,1.125 h0.5
  text "6" at 0.15,1.125 h0.5
  text "'.Designator'" at -2,-0.5 h0.75
  text "EP" at -0.25,-0.125 h0.5
M16-Top Courtyard:
  lines w0.01: -1.7,-1.9 -1.7,1.9 1.7,1.9 1.7,-1.9 -1.7,-1.9
3D body: height 1.01, standoff 1, extent -1.087,-1.317 -0.688,-0.918
3D body: height 1, standoff 0, extent -1.5,-1.5 1.5,1.5

## ICC_VFQFPN8-EPAD_4X4_P080 [mm] "MCD-02219"
height 1
pads (9):
  rect 0.3x0.85 smd mask+0.05: 1(-1.2,-1.9) 2(-0.4,-1.9) 3(0.4,-1.9) 4(1.2,-1.9) 5(1.2,1.9) 6(0.4,1.9) 7(-0.4,1.9) 8(-1.2,1.9)
  rect 3x2.2 smd mask+0.05: 9(0,0)
Top Overlay:
  circle w0.254: c-1.675,-1.575 r0.075
  lines w0.12: -1.525,-2 -2,-2 -2,2 -1.525,2 ; 1.525,-2 2,-2 2,2 1.525,2
  text "1" at -2.475,-2.475 h1.5
M14-Top Assembly:
  circle w0.01: c-1.675,-1.575 r0.2
  lines w0.01: -1.35,-2 -1.35,-1.5 -1.05,-1.5 -1.05,-2 ; -1.35,2 -1.35,1.5 -1.05,1.5 -1.05,2 ; -0.55,-2 -0.55,-1.5 -0.25,-1.5 -0.25,-2 ; -0.55,2 -0.55,1.5 -0.25,1.5 -0.25,2 ; 0.25,-2 0.25,-1.5 0.55,-1.5 0.55,-2 ; 0.25,2 0.25,1.5 0.55,1.5 0.55,2 ; 1.05,-2 1.05,-1.5 1.35,-1.5 1.35,-2 ; 1.05,2 1.05,1.5 1.35,1.5 1.35,2 ; -2,-2 2,-2 2,2 -2,2 -2,-2 ; -1.5,-0.825 -1.225,-1.1 1.5,-1.1 1.5,1.1 -1.5,1.1 -1.5,-0.825
  text "9" at -0.15,-0.2 h0.65
  text "1" at -1.3,-1.95 h0.65
  text "4" at 1.05,-1.95 h0.65
  text "5" at 1.05,1.55 h0.65
  text "8" at -1.325,1.525 h0.65
  text "'.Designator'" at -2,-0.5 h0.75
M16-Top Courtyard:
  lines w0.01: -2.2,-2.475 -2.2,2.475 2.2,2.475 2.2,-2.475 -2.2,-2.475
3D body: height 1, standoff 0, extent -2,-2 2,2
3D body: height 1.1, standoff 1, extent -1.873,-1.774 -1.475,-1.375

## ICC_VFQFPN24-EPAD_4X4_P050 [mm] "MCD-04126"
height 0.8
pads (25):
  rect 0.55x0.25 smd mask+0.05: 1(-1.875,1.25) 2(-1.875,0.75) 3(-1.875,0.25) 4(-1.875,-0.25) 5(-1.875,-0.75) 6(-1.875,-1.25) 13(1.875,-1.25) 14(1.875,-0.75) 15(1.875,-0.25) 16(1.875,0.25) 17(1.875,0.75) 18(1.875,1.25)
  rect 0.25x0.55 smd mask+0.05: 7(-1.25,-1.875) 8(-0.75,-1.875) 9(-0.25,-1.875) 10(0.25,-1.875) 11(0.75,-1.875) 12(1.25,-1.875) 19(1.25,1.875) 20(0.75,1.875) 21(0.25,1.875) 22(-0.25,1.875) 23(-0.75,1.875) 24(-1.25,1.875)
  round 0.025 smd mask+0.05: 25(0,0)
Top Layer:
  region: -0.95,1.3 -1.3,0.95 -1.3,-1.3 1.3,-1.3 1.3,1.3
Top Overlay:
  text "1" at -2.825,1.225 h1.5
M14-Top Assembly:
  circle w0.01: c-1.85,1.85 r0.125
  lines w0.01: -2,-1.375 -1.725,-1.375 ccw(c-1.725,-1.25) -1.6,-1.25 ccw(c-1.725,-1.25) -1.725,-1.125 -2,-1.125 ; -2,-0.875 -1.725,-0.875 ccw(c-1.725,-0.75) -1.6,-0.75 ccw(c-1.725,-0.75) -1.725,-0.625 -2,-0.625 ; -2,-0.375 -1.725,-0.375 ccw(c-1.725,-0.25) -1.6,-0.25 ccw(c-1.725,-0.25) -1.725,-0.125 -2,-0.125 ; -2,0.125 -1.725,0.125 ccw(c-1.725,0.25) -1.6,0.25 ccw(c-1.725,0.25) -1.725,0.375 -2,0.375 ; -2,0.625 -1.725,0.625 ccw(c-1.725,0.75) -1.6,0.75 ccw(c-1.725,0.75) -1.725,0.875 -2,0.875 ; -2,1.125 -1.725,1.125 ccw(c-1.725,1.25) -1.6,1.25 ccw(c-1.725,1.25) -1.725,1.375 -2,1.375 ; -1.375,-2 -1.375,-1.725 cw(c-1.25,-1.725) -1.25,-1.6 cw(c-1.25,-1.725) -1.125,-1.725 -1.125,-2 ; -1.375,2 -1.375,1.725 ccw(c-1.25,1.725) -1.25,1.6 ccw(c-1.25,1.725) -1.125,1.725 -1.125,2 ; -0.875,-2 -0.875,-1.725 cw(c-0.75,-1.725) -0.75,-1.6 cw(c-0.75,-1.725) -0.625,-1.725 -0.625,-2 ; -0.875,2 -0.875,1.725 ccw(c-0.75,1.725) -0.75,1.6 ccw(c-0.75,1.725) -0.625,1.725 -0.625,2 ; -0.375,-2 -0.375,-1.725 cw(c-0.25,-1.725) -0.25,-1.6 cw(c-0.25,-1.725) -0.125,-1.725 -0.125,-2 ; -0.375,2 -0.375,1.725 ccw(c-0.25,1.725) -0.25,1.6 ccw(c-0.25,1.725) -0.125,1.725 -0.125,2 ; 0.125,-2 0.125,-1.725 cw(c0.25,-1.725) 0.25,-1.6 cw(c0.25,-1.725) 0.375,-1.725 0.375,-2 ; 0.125,2 0.125,1.725 ccw(c0.25,1.725) 0.25,1.6 ccw(c0.25,1.725) 0.375,1.725 0.375,2 ; 0.625,-2 0.625,-1.725 cw(c0.75,-1.725) 0.75,-1.6 cw(c0.75,-1.725) 0.875,-1.725 0.875,-2 ; 0.625,2 0.625,1.725 ccw(c0.75,1.725) 0.75,1.6 ccw(c0.75,1.725) 0.875,1.725 0.875,2 ; 1.125,-2 1.125,-1.725 cw(c1.25,-1.725) 1.25,-1.6 cw(c1.25,-1.725) 1.375,-1.725 1.375,-2 ; 1.125,2 1.125,1.725 ccw(c1.25,1.725) 1.25,1.6 ccw(c1.25,1.725) 1.375,1.725 1.375,2 ; 2,-1.375 1.725,-1.375 cw(c1.725,-1.25) 1.6,-1.25 cw(c1.725,-1.25) 1.725,-1.125 2,-1.125 ; 2,-0.875 1.725,-0.875 cw(c1.725,-0.75) 1.6,-0.75 cw(c1.725,-0.75) 1.725,-0.625 2,-0.625 ; 2,-0.375 1.725,-0.375 cw(c1.725,-0.25) 1.6,-0.25 cw(c1.725,-0.25) 1.725,-0.125 2,-0.125 ; 2,0.125 1.725,0.125 cw(c1.725,0.25) 1.6,0.25 cw(c1.725,0.25) 1.725,0.375 2,0.375 ; 2,0.625 1.725,0.625 cw(c1.725,0.75) 1.6,0.75 cw(c1.725,0.75) 1.725,0.875 2,0.875 ; 2,1.125 1.725,1.125 cw(c1.725,1.25) 1.6,1.25 cw(c1.725,1.25) 1.725,1.375 2,1.375 ; -2,-2 -2,2 2,2 2,-2 -2,-2 ; -1.35,-1.35 -1.35,1.35 1.35,1.35 1.35,-1.35 -1.35,-1.35
  text "24" at -1.5,1.55 h0.65
  text "19" at 0.9,1.55 h0.65
  text "18" at 1.475,1 h0.65
  text "13" at 1.475,-1.4 h0.65
  text "12" at 0.9,-1.95 h0.65
  text "7" at -1.3,-1.95 h0.65
  text "6" at -1.9,-1.375 h0.65
  text "'.Designator'" at -2,-0.5 h0.75
  text "1" at -1.9,1.025 h0.65
  text "25" at -0.325,-0.2 h0.65
M16-Top Courtyard:
  lines w0.01: -2.3,-2.3 2.3,-2.3 2.3,2.3 -2.3,2.3 -2.3,-2.3
3D body: height 0.81, standoff 0.8, extent -1.925,1.525 -1.525,1.925
3D body: height 0.8, standoff 0, extent -2,-2 2,2

## ICC_VFQFPN28-EPAD_4X4_P040 [mm]
height 1
pads (29):
  rect 0.65x0.2 smd mask+0.05: 1(-1.9,1.2) 2(-1.9,0.8) 3(-1.9,0.4) 4(-1.9,0) 5(-1.9,-0.4) 6(-1.9,-0.8) 7(-1.9,-1.2) 15(1.9,-1.2) 16(1.9,-0.8) 17(1.9,-0.4) 18(1.9,0) 19(1.9,0.4) 20(1.9,0.8) 21(1.9,1.2)
  rect 0.2x0.65 smd mask+0.05: 8(-1.2,-1.9) 9(-0.8,-1.9) 10(-0.4,-1.9) 11(0,-1.9) 12(0.4,-1.9) 13(0.8,-1.9) 14(1.2,-1.9) 22(1.2,1.9) 23(0.8,1.9) 24(0.4,1.9) 25(0,1.9) 26(-0.4,1.9) 27(-0.8,1.9) 28(-1.2,1.9)
  rect 2.7x2.7 smd mask+0.05: 29(0,0)
Top Overlay:
  text "1" at -2.825,1.225 h1.5
M14-Top Assembly:
  circle w0.01: c-1.85,1.85 r0.125
  lines w0.01: -2,-1.325 -1.675,-1.325 ccw(c-1.675,-1.2) -1.55,-1.2 ccw(c-1.675,-1.2) -1.675,-1.075 -2,-1.075 ; -2,-0.925 -1.675,-0.925 ccw(c-1.675,-0.8) -1.55,-0.8 ccw(c-1.675,-0.8) -1.675,-0.675 ; -2,-0.675 -1.675,-0.675 ; -2,-0.525 -1.675,-0.525 ccw(c-1.675,-0.4) -1.55,-0.4 ccw(c-1.675,-0.4) -1.675,-0.275 -2,-0.275 ; -2,-0.125 -1.675,-0.125 ccw(c-1.675,0) -1.55,0 ccw(c-1.675,0) -1.675,0.125 -2,0.125 ; -2,0.275 -1.675,0.275 ccw(c-1.675,0.4) -1.55,0.4 ccw(c-1.675,0.4) -1.675,0.525 -2,0.525 ; -2,0.675 -1.675,0.675 ; -2,0.925 -1.675,0.925 cw(c-1.675,0.8) -1.55,0.8 cw(c-1.675,0.8) -1.675,0.675 ; -2,1.075 -1.675,1.075 ccw(c-1.675,1.2) -1.55,1.2 ccw(c-1.675,1.2) -1.675,1.325 -2,1.325 ; -1.325,-2 -1.325,-1.675 cw(c-1.2,-1.675) -1.2,-1.55 cw(c-1.2,-1.675) -1.075,-1.675 -1.075,-2 ; -1.325,2 -1.325,1.675 ccw(c-1.2,1.675) -1.2,1.55 ccw(c-1.2,1.675) -1.075,1.675 -1.075,2 ; -0.925,-2 -0.925,-1.675 cw(c-0.8,-1.675) -0.8,-1.55 cw(c-0.8,-1.675) -0.675,-1.675 ; -0.925,2 -0.925,1.675 ccw(c-0.8,1.675) -0.8,1.55 ccw(c-0.8,1.675) -0.675,1.675 ; -0.675,-2 -0.675,-1.675 ; -0.675,1.675 -0.675,2 ; -0.525,-2 -0.525,-1.675 cw(c-0.4,-1.675) -0.4,-1.55 cw(c-0.4,-1.675) -0.275,-1.675 -0.275,-2 ; -0.525,2 -0.525,1.675 ccw(c-0.4,1.675) -0.4,1.55 ccw(c-0.4,1.675) -0.275,1.675 -0.275,2 ; -0.125,-2 -0.125,-1.675 cw(c0,-1.675) 0,-1.55 cw(c0,-1.675) 0.125,-1.675 0.125,-2 ; -0.125,2 -0.125,1.675 ccw(c0,1.675) 0,1.55 ccw(c0,1.675) 0.125,1.675 0.125,2 ; 0.275,-2 0.275,-1.675 cw(c0.4,-1.675) 0.4,-1.55 cw(c0.4,-1.675) 0.525,-1.675 0.525,-2 ; 0.275,2 0.275,1.675 ccw(c0.4,1.675) 0.4,1.55 ccw(c0.4,1.675) 0.525,1.675 0.525,2 ; 0.675,-1.675 cw(c0.8,-1.675) 0.8,-1.55 cw(c0.8,-1.675) 0.925,-1.675 0.925,-2 ; 0.675,1.675 ccw(c0.8,1.675) 0.8,1.55 ccw(c0.8,1.675) 0.925,1.675 0.925,2 ; 0.675,-2 0.675,-1.675 ; 0.675,1.675 0.675,2 ; 1.075,-2 1.075,-1.675 cw(c1.2,-1.675) 1.2,-1.55 cw(c1.2,-1.675) 1.325,-1.675 1.325,-2 ; 1.075,2 1.075,1.675 ccw(c1.2,1.675) 1.2,1.55 ccw(c1.2,1.675) 1.325,1.675 1.325,2 ; 1.675,-0.675 2,-0.675 ; 1.675,-0.675 ccw(c1.675,-0.8) 1.55,-0.8 ccw(c1.675,-0.8) 1.675,-0.925 2,-0.925 ; 1.675,0.675 cw(c1.675,0.8) 1.55,0.8 cw(c1.675,0.8) 1.675,0.925 2,0.925 ; 1.675,0.675 2,0.675 ; 2,-1.325 1.675,-1.325 cw(c1.675,-1.2) 1.55,-1.2 cw(c1.675,-1.2) 1.675,-1.075 2,-1.075 ; 2,-0.525 1.675,-0.525 cw(c1.675,-0.4) 1.55,-0.4 cw(c1.675,-0.4) 1.675,-0.275 2,-0.275 ; 2,-0.125 1.675,-0.125 cw(c1.675,0) 1.55,0 cw(c1.675,0) 1.675,0.125 2,0.125 ; 2,0.275 1.675,0.275 cw(c1.675,0.4) 1.55,0.4 cw(c1.675,0.4) 1.675,0.525 2,0.525 ; 2,1.075 1.675,1.075 cw(c1.675,1.2) 1.55,1.2 cw(c1.675,1.2) 1.675,1.325 2,1.325 ; -2,-2 2,-2 2,2 -2,2 -2,-2 ; -1.4,-1.4 1.4,-1.4 1.4,1.4 -1.4,1.4 -1.4,-1.4
  text "29" at -0.325,-0.2 h0.65
  text "1" at -1.9,1.025 h0.65
  text "'.Designator'" at -2,-0.5 h0.75
  text "7" at -1.9,-1.375 h0.65
  text "8" at -1.3,-1.95 h0.65
  text "14" at 0.9,-1.95 h0.65
  text "15" at 1.475,-1.4 h0.65
  text "21" at 1.475,1 h0.65
  text "22" at 0.9,1.55 h0.65
  text "28" at -1.5,1.55 h0.65
M16-Top Courtyard:
  lines w0.01: -2.375,-2.375 -2.375,2.375 2.375,2.375 2.375,-2.375 -2.375,-2.375
3D body: height 1, standoff 0, extent -2,-2 2,2
3D body: height 1.1, standoff 1, extent -1.923,1.525 -1.525,1.925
